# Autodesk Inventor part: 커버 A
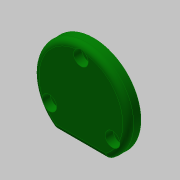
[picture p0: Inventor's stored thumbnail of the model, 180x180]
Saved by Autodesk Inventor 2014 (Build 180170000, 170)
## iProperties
Created: 2020-04
Part Number: 커버 A
Material: 알루미늄 6061
Document SubType Name: Modeling
Designer: mduedu
Density: 2.71 g/cm^3
Mass: 30.8954 g
Surface Area: 61.0157 cm^2
Volume: 11.4005 cm^3
Appearance: 진녹색
Author: mduedu
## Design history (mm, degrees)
sketch "스케치1"
  geometry: C1 r 26 at (0, 0); 1 further point
  constraints: 1 centre point, 1 coincident
  dimensions: "d0" = 52 diameter of C1
extrude "돌출1" new body sketch "스케치1" distance "d1" = 7; taper "d2" = 0 deg
sketch "스케치2"
  geometry: L1 (-14.62, -21.5)-(14.62, -21.5); A1 r 26 centre (0, 0) between (-14.62, -21.5) and (14.62, -21.5) reference; 1 further point
  constraints: 2 end point, 2 point on circle, 1 horizontal
  dimensions: "d3" = 21.5 distance from line of L1 point (0, 0)
extrude "돌출2" cut sketch "스케치2" stored distance "d4" = 7; taper "d5" = 0 deg
fillet "모깎기1" dims "d6" = 3
fillet "모깎기2" dims "d7" = 3
sketch "스케치3" dims "d8" = 40
  geometry: 3 further points
  constraints: 2 vertical alignment, 1 coincident, 2 other
hole "구멍1" sketch "스케치3" at (0, 20) diameter "d9" = 4.5; stored, may be unused: countersink angle "d13" = 90 deg, drill point angle "d15" = 118 deg; dims "d10" = 6, "d11" = 8, "d12" = 4.4, "d14" = 8
sketch "스케치4"
  geometry: C1 r 16 at (0, 0); 1 further point
  constraints: 1 centre point, 1 coincident
  dimensions: "d19" = 32 diameter of C1
extrude "돌출3" join sketch "스케치4" distance "d20" = 3; taper "d21" = 0 deg
sketch "스케치5"
  geometry: C1 r 14 at (0, 0); 1 further point
  constraints: 1 centre point, 1 coincident
  dimensions: "d22" = 28 diameter of C1
extrude "돌출4" cut sketch "스케치5" distance "d23" = 7; taper "d24" = 0 deg
fillet "모깎기3" dims "d25" = 3
chamfer "모따기1" distance "d26" = 0.5; stored, may be unused: second distance "d27" = 2, angle "d28" = 45 deg
node "솔리드1"
pattern_circular "원형 패턴1" dims angle "d17" = 360 deg
node "투영된 루프1"
